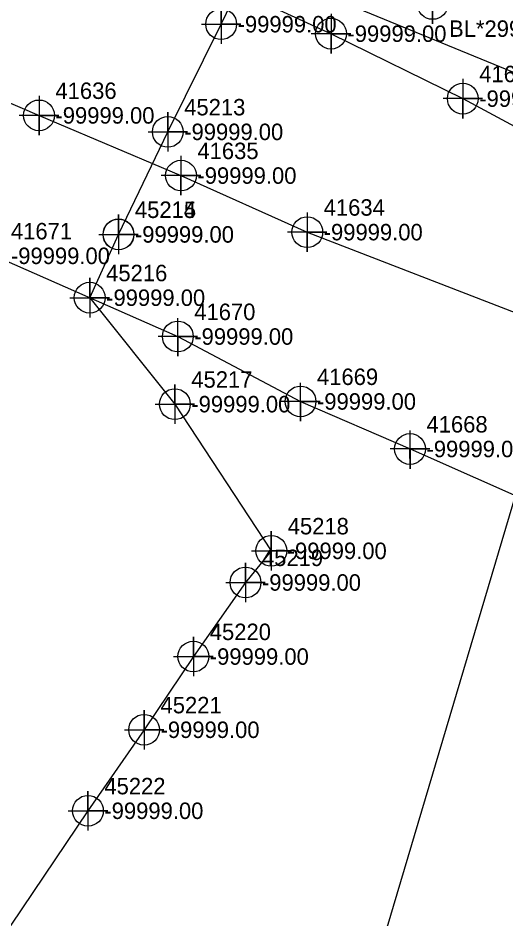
# Model space of a CAD drawing. Extents: x 2083698 to 2094313, y 743246 to 752873.
# Drawn here: x 2093450.4 to 2093524.6, y 743794.1 to 743931 of the extents above; entities that cross this region are included whole.
import ezdxf

# ---------------------------------------------------------------- set-up
doc = ezdxf.new("R2010")
doc.units = 0
for name, color, linetype in [('COGO Default Chain', 7, 'Continuous'), ('COGO Default Curve', 7, 'Continuous'), ('COGO Default Point Number', 7, 'Continuous'), ('Exist Property Line', 7, 'Continuous'), ('Exist Right of Way Line', 7, 'Continuous'), ('Exist Right of Way Line Leader', 7, 'Continuous'), ('Exist Right of Way Line Text', 7, 'Continuous'), ('Exist Right of Way Width CELL', 7, 'Continuous'), ('Exist Utilities Gas UG Line SUE LOS B', 7, 'Continuous'), ('Exist Utilities Power UG Cable SUE LOS C', 7, 'Continuous'), ('Exist Utilities Telephone UG Conduit SUE LOS B', 7, 'Continuous'), ('Exist Utilities Water UG Line SUE LOS B', 7, 'Continuous'), ('Old_Level_20', 7, 'Continuous'), ('Scratch_Level_2', 7, 'Continuous')]:
    doc.layers.add(name, color=color, linetype=linetype)

msp = doc.modelspace()

# ---------------------------------------------------------------- linework, layer by layer
at = {"layer": 'COGO Default Curve'}
for points in [[(2093478.31, 743930.03), (2093484.31, 743930.03), (2093481.31, 743930.03), (2093481.31, 743933.03), (2093481.31, 743927.03)], [(2093470.19, 743913.67), (2093476.19, 743913.67), (2093473.19, 743913.67), (2093473.19, 743916.67), (2093473.19, 743910.67)], [(2093462.69, 743898.09), (2093468.69, 743898.09), (2093465.69, 743898.09), (2093465.69, 743901.09), (2093465.69, 743895.09)], [(2093462.7, 743898.08), (2093468.7, 743898.08), (2093465.7, 743898.08), (2093465.7, 743901.08), (2093465.7, 743895.08)], [(2093458.32, 743888.47), (2093464.32, 743888.47), (2093461.32, 743888.47), (2093461.32, 743891.47), (2093461.32, 743885.47)], [(2093471.27, 743872.29), (2093477.27, 743872.29), (2093474.27, 743872.29), (2093474.27, 743875.29), (2093474.27, 743869.29)], [(2093485.93, 743850), (2093491.93, 743850), (2093488.93, 743850), (2093488.93, 743853), (2093488.93, 743847)], [(2093482.01, 743845.19), (2093488.01, 743845.19), (2093485.01, 743845.19), (2093485.01, 743848.19), (2093485.01, 743842.19)], [(2093474.08, 743833.94), (2093480.08, 743833.94), (2093477.08, 743833.94), (2093477.08, 743836.94), (2093477.08, 743830.94)], [(2093466.59, 743822.81), (2093472.59, 743822.81), (2093469.59, 743822.81), (2093469.59, 743825.81), (2093469.59, 743819.81)], [(2093458.05, 743810.5), (2093464.05, 743810.5), (2093461.05, 743810.5), (2093461.05, 743813.5), (2093461.05, 743807.5)]]:
    msp.add_lwpolyline(points, dxfattribs=at)
for centre in [(2093481.31, 743930.03), (2093473.19, 743913.67), (2093465.69, 743898.09), (2093465.7, 743898.08), (2093461.32, 743888.47), (2093474.27, 743872.29), (2093488.93, 743850), (2093485.01, 743845.19), (2093477.08, 743833.94), (2093469.59, 743822.81), (2093461.05, 743810.5)]:
    msp.add_circle(centre, 2.34, dxfattribs=at)
at = {"layer": 'COGO Default Point Number'}
for points in [[(2093513.46, 743936.11), (2093513.46, 743930.11), (2093513.46, 743933.11), (2093516.46, 743933.11), (2093510.46, 743933.11)], [(2093498.01, 743931.59), (2093498.01, 743925.59), (2093498.01, 743928.59), (2093501.01, 743928.59), (2093495.01, 743928.59)], [(2093518.05, 743921.72), (2093518.05, 743915.72), (2093518.05, 743918.72), (2093521.05, 743918.72), (2093515.05, 743918.72)], [(2093453.61, 743919.17), (2093453.61, 743913.17), (2093453.61, 743916.17), (2093456.61, 743916.17), (2093450.61, 743916.17)], [(2093475.2, 743910.03), (2093475.2, 743904.03), (2093475.2, 743907.03), (2093478.2, 743907.03), (2093472.2, 743907.03)], [(2093494.4, 743901.43), (2093494.4, 743895.43), (2093494.4, 743898.43), (2093497.4, 743898.43), (2093491.4, 743898.43)]]:
    msp.add_lwpolyline(points, dxfattribs=at)
for centre in [(2093513.46, 743933.11), (2093498.01, 743928.59), (2093518.05, 743918.72), (2093453.61, 743916.17), (2093475.2, 743907.03), (2093494.4, 743898.43)]:
    msp.add_circle(centre, 2.34, dxfattribs=at)
at = {"layer": 'Exist Right of Way Line Text'}
for points in [[(2093474.69, 743885.38), (2093474.72, 743879.57), (2093474.7, 743882.57), (2093477.72, 743882.57), (2093471.72, 743882.57)], [(2093493.34, 743875.51), (2093493.38, 743869.7), (2093493.36, 743872.7), (2093496.38, 743872.7), (2093490.38, 743872.7)], [(2093509.99, 743868.29), (2093510.03, 743862.48), (2093510.01, 743865.48), (2093513.03, 743865.48), (2093507.03, 743865.48)]]:
    msp.add_lwpolyline(points, dxfattribs=at)
for centre in [(2093474.72, 743882.57), (2093493.38, 743872.7), (2093510.03, 743865.48)]:
    msp.add_circle(centre, 2.34, dxfattribs=at)
at = {"layer": 'Exist Utilities Gas UG Line SUE LOS B'}
for points in [[(2093461.32, 743888.47), (2093465.7, 743898.08), (2093465.69, 743898.09), (2093473.19, 743913.67), (2093481.31, 743930.03), (2093487.86, 743943.58), (2093493.95, 743956.81), (2093500.47, 743972.46), (2093510.53, 743993.72), (2093512.09, 744000.13)], [(2093461.32, 743888.47), (2093474.27, 743872.29), (2093488.93, 743850), (2093485.01, 743845.19), (2093477.08, 743833.94), (2093469.59, 743822.81), (2093461.05, 743810.5), (2093444.26, 743785.67)]]:
    msp.add_lwpolyline(points, dxfattribs=at)
at = {"layer": 'Exist Utilities Power UG Cable SUE LOS C'}
msp.add_line((2093454.44, 743617.61), (2093577.14, 744030.24), dxfattribs=at)
at = {"layer": 'Exist Utilities Telephone UG Conduit SUE LOS B'}
for points in [[(2093310.54, 744009.39), (2093322.82, 744005.22), (2093337.8, 744000.12), (2093362.38, 743991.33), (2093380.04, 743987.01), (2093399.67, 743981.23), (2093409.84, 743974.58), (2093429.84, 743965.45), (2093441.05, 743960.44), (2093457.35, 743953.23), (2093481.49, 743942.3), (2093498.19, 743934.07), (2093529.55, 743921.16), (2093547.3, 743911.89), (2093561.14, 743905.22), (2093576.9, 743897.18), (2093595.77, 743886.69), (2093600.65, 743883.85), (2093611.31, 743876.33), (2093624.4, 743867.89), (2093638.39, 743859.54), (2093654.22, 743849.48), (2093714.03, 743810.35)], [(2093324.3, 743948.7), (2093331.1, 743945.44), (2093343.36, 743940.7), (2093356.52, 743934.29), (2093366.84, 743929.01), (2093384.31, 743921.55), (2093404.33, 743913.58), (2093426.28, 743903.99), (2093446.84, 743894.83), (2093474.72, 743882.57), (2093493.38, 743872.7), (2093510.03, 743865.48), (2093529.94, 743856.7), (2093545.64, 743848.5), (2093554.16, 743844.45), (2093555.75, 743843.36)]]:
    msp.add_lwpolyline(points, dxfattribs=at)
at = {"layer": 'Exist Utilities Water UG Line SUE LOS B'}
for points in [[(2093309.19, 743997.25), (2093330.81, 743991.1), (2093356.56, 743984.1), (2093379.55, 743977.39), (2093396.23, 743971.73), (2093406.3, 743968.8), (2093428.33, 743959.72), (2093438.72, 743955.11), (2093456.01, 743947.42), (2093480.23, 743936.82), (2093480.35, 743936.7), (2093498.01, 743928.59), (2093518.05, 743918.72), (2093537.94, 743908.07), (2093560.07, 743893.77)], [(2093301.62, 743969.21), (2093335.27, 743960.32), (2093367.08, 743950.37), (2093388.86, 743942.65), (2093404.38, 743937.04), (2093423.81, 743928.99), (2093453.61, 743916.17), (2093475.2, 743907.03), (2093494.4, 743898.43), (2093527.71, 743885.56), (2093539.87, 743878.66), (2093540.83, 743878.08)]]:
    msp.add_lwpolyline(points, dxfattribs=at)

# ---------------------------------------------------------------- texts
at = {"layer": 'COGO Default Chain'}
for p in [(2093483.81, 743928.78), (2093475.69, 743912.42), (2093468.19, 743896.84), (2093468.2, 743896.83), (2093463.82, 743887.22), (2093476.77, 743871.04), (2093491.43, 743848.75), (2093487.51, 743843.94), (2093479.58, 743832.69), (2093472.09, 743821.56), (2093463.55, 743809.25)]:
    msp.add_text('-99999.00', height=2.5, dxfattribs=at).set_placement(p)
at = {"layer": 'Exist Property Line'}
for p in [(2093500.51, 743927.34), (2093520.55, 743917.47), (2093456.11, 743914.92), (2093477.7, 743905.78), (2093496.9, 743897.18)]:
    msp.add_text('-99999.00', height=2.5, dxfattribs=at).set_placement(p)
at = {"layer": 'Exist Right of Way Line'}
for s, p in [('41655', (2093520.55, 743921.22)), ('41636', (2093456.11, 743918.67)), ('41635', (2093477.7, 743909.53)), ('41634', (2093496.9, 743900.93))]:
    msp.add_text(s, height=2.5, dxfattribs=at).set_placement(p)
at = {"layer": 'Exist Right of Way Line Leader'}
for s, p in [('41671', (2093449.34, 743897.33)), ('41670', (2093477.22, 743885.07)), ('41669', (2093495.88, 743875.2)), ('41668', (2093512.53, 743867.98))]:
    msp.add_text(s, height=2.5, dxfattribs=at).set_placement(p)
at = {"layer": 'Exist Right of Way Width CELL'}
msp.add_text('BL*2991', height=2.5, dxfattribs=at).set_placement((2093515.96, 743928.11))
at = {"layer": 'Old_Level_20'}
for s, p in [('45213', (2093475.69, 743916.17)), ('45214', (2093468.19, 743900.59)), ('45215', (2093468.2, 743900.58)), ('45216', (2093463.82, 743890.97)), ('45217', (2093476.77, 743874.79)), ('45218', (2093491.43, 743852.5)), ('45219', (2093487.51, 743847.69)), ('45220', (2093479.58, 743836.44)), ('45221', (2093472.09, 743825.31)), ('45222', (2093463.55, 743813))]:
    msp.add_text(s, height=2.5, dxfattribs=at).set_placement(p)
at = {"layer": 'Scratch_Level_2'}
for p in [(2093449.34, 743893.58), (2093477.22, 743881.32), (2093495.88, 743871.45), (2093512.53, 743864.23)]:
    msp.add_text('-99999.00', height=2.5, dxfattribs=at).set_placement(p)

doc.saveas('drawing.dxf')
